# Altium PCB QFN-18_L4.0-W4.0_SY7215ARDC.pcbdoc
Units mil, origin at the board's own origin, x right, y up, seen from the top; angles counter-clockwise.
Board outline 696.4 x 667.68 mil, 2 copper layers (Top Layer, Bottom Layer), stack 0 mil thick; 1 components, 0 nets, 18 pads, 0 vias.
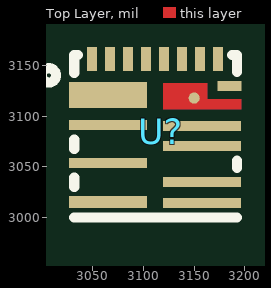
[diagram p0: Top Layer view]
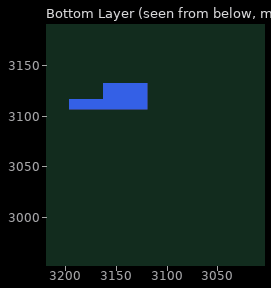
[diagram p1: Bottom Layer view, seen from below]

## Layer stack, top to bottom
Top Layer: signal copper (thickness not stored)
Bottom Layer: signal copper (thickness not stored)

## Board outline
3446.4,2750 2750,2750 2750,3417.68 3446.4,3417.68

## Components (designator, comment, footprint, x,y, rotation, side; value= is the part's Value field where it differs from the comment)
U? "" QFN-18_L4.0-W4.0_SY7215ARDC 3117.07,3085 r0 top

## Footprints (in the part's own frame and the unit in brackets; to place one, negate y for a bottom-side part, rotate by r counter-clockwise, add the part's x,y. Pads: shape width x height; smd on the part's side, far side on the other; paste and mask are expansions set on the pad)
QFN-18_L4.0-W4.0_SY7215ARDC [mm]
  rect 1.95x0.65 smd: 1(-1.31,0.9)
  rect 1.95x0.25 smd: 2(-1.31,0.15) 3(-1.31,-0.8) 5(1.04,-1.8) 6(1.04,-1.275) 7(1.04,-0.375) 8(1.04,0.125)
  rect 1.95x0.3 smd: 4(-1.31,-1.775)
  round 0.279 smd: 9(0.838,0.829)
  rect 0.6x0.25 smd: 10(1.715,1.125)
  rect 0.25x0.6 smd: 11(1.435,1.8) 12(0.985,1.8) 13(0.535,1.8) 14(0.085,1.8) 15(-0.365,1.8) 16(-0.815,1.8) 17(-1.265,1.8) 18(-1.715,1.8)
  Top Layer region: 0.065,1.2 0.065,0.55 0.065,0.55 1.165,0.55 2.015,0.55 2.015,0.8 1.165,0.8 1.165,1.2
  Bottom Layer region: 0.065,1.2 0.065,0.55 0.065,0.55 1.165,0.55 2.015,0.55 2.015,0.8 1.165,0.8 1.165,1.2
  Multi-Layer region: 0.065,1.2 0.065,0.55 0.065,0.55 1.165,0.55 2.015,0.55 2.015,0.8 1.165,0.8 1.165,1.2
  silkscreen extent -2.97,-2.16 1.91,1.91

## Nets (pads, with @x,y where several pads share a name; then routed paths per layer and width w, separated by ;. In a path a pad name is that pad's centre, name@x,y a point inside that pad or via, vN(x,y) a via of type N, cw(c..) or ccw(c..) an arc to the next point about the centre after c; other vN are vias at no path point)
pads on no net: U?.1 U?.2 U?.3 U?.4 U?.5 U?.6 U?.7 U?.8 U?.9 U?.10 U?.11 U?.12 U?.13 U?.14 U?.15 U?.16 U?.17 U?.18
